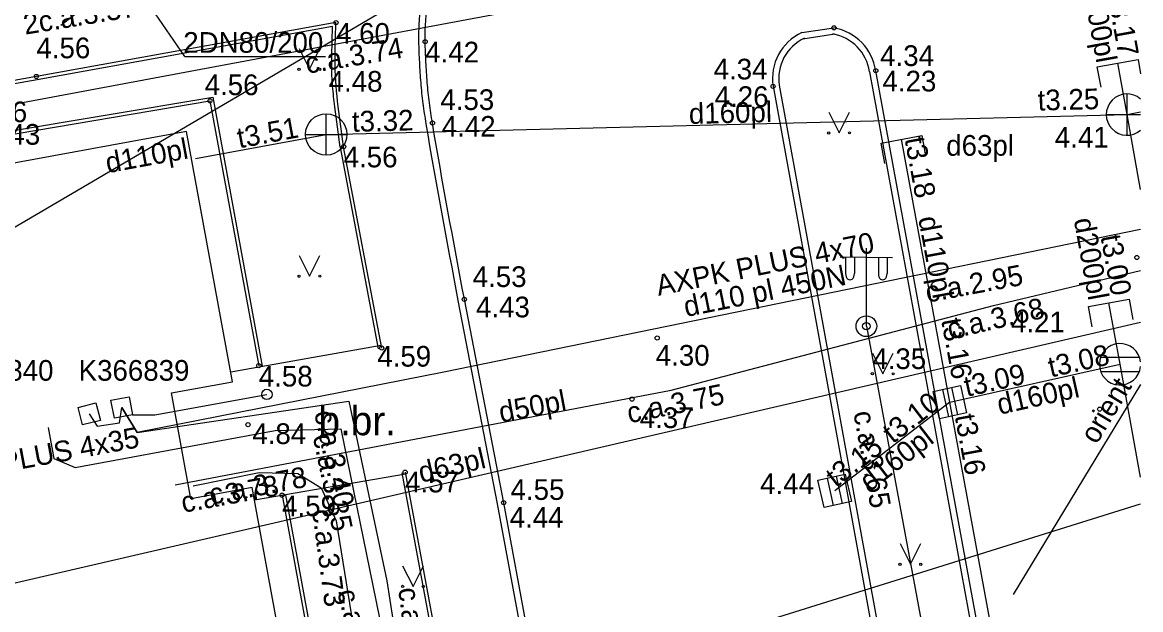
# Model space of a CAD drawing. Extents: x 484635 to 484808, y 278866 to 278977.
# Drawn here: x 484780.57 to 484807.57, y 278884.44 to 278898.63 of the extents above; entities that cross this region are included whole.
import ezdxf

# ---------------------------------------------------------------- set-up
doc = ezdxf.new("R2010")
doc.units = 0
for name, color, linetype in [('APGS_ACRL_####_####_#', 7, 'Continuous'), ('APGS_ELEM_####_####_#', 7, 'Continuous'), ('APGS_ELEM_####_TKST_#', 7, 'Continuous'), ('APGS_VADP_ZSPR_####_I', 7, 'Continuous'), ('BUVE_EKAS_####_####_#', 7, 'Continuous'), ('CELI_CAPM_####_####_#', 7, 'Continuous'), ('CELI_CMAL_####_####_#', 7, 'Continuous'), ('CELI_CSEG_####_TKST_#', 7, 'Continuous'), ('CKOM_ELEM_####_####_#', 7, 'Continuous'), ('CKOM_ZEMJ_####_####_#', 7, 'Continuous'), ('DREN_ELEM_####_####_#', 7, 'Continuous'), ('DREN_VADP_####_####_I', 7, 'Continuous'), ('DREN_VADP_####_TKST_I', 7, 'Continuous'), ('ELEK_ACRL_####_####_#', 7, 'Continuous'), ('ELEK_ACRL_####_TKST_#', 7, 'Continuous'), ('ELEK_ELEM_####_####_#', 7, 'Continuous'), ('ELEK_ELEM_####_TKST_#', 7, 'Continuous'), ('ELEK_VADP_ZSPR_####_I', 7, 'Continuous'), ('ELEK_VADP_ZSPR_TKST_I', 7, 'Continuous'), ('LKAN_ELEM_####_####_#', 7, 'Continuous'), ('LKAN_ELEM_PAST_TKST_#', 7, 'Continuous'), ('LKAN_VADP_PAST_####_#', 7, 'Continuous'), ('LKAN_VADP_PAST_####_I', 7, 'Continuous'), ('LKAN_VADP_PAST_TKST_I', 7, 'Continuous'), ('RELJ_AATZ_####_TKST_#', 7, 'Continuous'), ('RELJ_ELEM_####_####_#', 7, 'Continuous'), ('SAKK_KKAN_####_####_I', 7, 'Continuous'), ('SAKK_KKAN_####_TKST_I', 7, 'Continuous'), ('SAKT_VADP_NEDR_####_#', 7, 'Continuous'), ('SAKT_VADP_NEDR_TKST_#', 7, 'Continuous'), ('SILT_VADP_UDEN_TKST_I', 7, 'Continuous'), ('SKAN_ELEM_####_####_#', 7, 'Continuous'), ('SKAN_ELEM_PAST_TKST_#', 7, 'Continuous'), ('SKAN_VADP_NEDR_####_#', 7, 'Continuous'), ('SKAN_VADP_PAST_####_I', 7, 'Continuous'), ('SKAN_VADP_PAST_TKST_I', 7, 'Continuous'), ('TERT_ELEM_####_####_#', 7, 'Continuous'), ('UDTK_VADP_NEDR_####_#', 7, 'Continuous'), ('UDTK_VADP_UDEN_####_I', 7, 'Continuous'), ('UDTK_VADP_UDEN_TKST_I', 7, 'Continuous')]:
    doc.layers.add(name, color=color, linetype=linetype)

msp = doc.modelspace()

# ---------------------------------------------------------------- linework, layer by layer
at = {"layer": 'APGS_ACRL_####_####_#'}
msp.add_lwpolyline([(484800.949, 278891.291), (484804.267, 278873.397), (484805.658, 278866.043)], dxfattribs=at)
at = {"layer": 'APGS_ELEM_####_####_#'}
for p, q in [((484800.949, 278891.291), (484800.949, 278893.174)), ((484800.949, 278892.958), (484800.314, 278892.953)), ((484800.449, 278892.954), (484800.449, 278892.562)), ((484800.659, 278892.956), (484800.659, 278892.562)), ((484800.949, 278892.958), (484801.584, 278892.953)), ((484801.239, 278892.956), (484801.239, 278892.562)), ((484801.449, 278892.954), (484801.449, 278892.562))]:
    msp.add_line(p, q, dxfattribs=at)
for radius in [0.25, 0.09]:
    msp.add_circle((484800.949, 278891.291), radius, dxfattribs=at)
for centre, major_axis, start_param, end_param in [((484800.554, 278892.562), (0, 0.151), 1.570796, 4.712389), ((484801.344, 278892.562), (0, -0.151), 4.712389, 7.853982)]:
    msp.add_ellipse(centre, major_axis=major_axis, ratio=0.695971, start_param=start_param, end_param=end_param, dxfattribs=at)
at = {"layer": 'APGS_VADP_ZSPR_####_I'}
msp.add_lwpolyline([(484800.949, 278891.291), (484804.267, 278873.397), (484805.658, 278866.043)], dxfattribs=at)
at = {"layer": 'BUVE_EKAS_####_####_#'}
for p, q in [((484784.53, 278895.998), (484773.318, 278893.935)), ((484785.643, 278889.949), (484784.53, 278895.998)), ((484784.168, 278889.678), (484785.643, 278889.949)), ((484784.638, 278887.121), (484784.168, 278889.678)), ((484786.113, 278887.392), (484784.638, 278887.121)), ((484787.226, 278881.344), (484786.113, 278887.392))]:
    msp.add_line(p, q, dxfattribs=at)
at = {"layer": 'CELI_CAPM_####_####_#'}
for p, q in [((484788.14, 278898.629), (484780.905, 278897.327)), ((484788.058, 278898.533), (484780.919, 278897.248)), ((484799.391, 278898.387), (484800.167, 278898.503)), ((484799.413, 278898.238), (484800.19, 278898.355)), ((484780.905, 278897.327), (484773.429, 278895.967)), ((484780.92, 278897.248), (484773.473, 278895.893)), ((484779.629, 278895.897), (484785.162, 278896.83)), ((484785.162, 278896.83), (484786.359, 278890.324)), ((484779.642, 278895.818), (484785.097, 278896.738)), ((484785.097, 278896.738), (484786.275, 278890.335)), ((484789.167, 278890.748), (484788.245, 278895.615)), ((484789.245, 278890.763), (484788.324, 278895.63)), ((484792.044, 278886.996), (484791.093, 278891.913)), ((484792.191, 278887.024), (484791.241, 278891.942)), ((484793.728, 278877.892), (484792.044, 278886.997)), ((484793.875, 278877.919), (484792.191, 278887.024))]:
    msp.add_line(p, q, dxfattribs=at)
for points in [[(484806.787, 278866.043), (484804.221, 278880.039), (484801.029, 278897.438)], [(484806.939, 278866.043), (484804.369, 278880.066), (484801.177, 278897.465)], [(484798.696, 278897.09), (484801.688, 278880.665), (484804.352, 278866.043)], [(484798.844, 278897.117), (484801.835, 278880.691), (484804.505, 278866.043)], [(484789.731, 278887.748), (484790.96, 278881.112), (484791.811, 278876.364)], [(484789.809, 278887.762), (484791.039, 278881.126), (484791.89, 278876.378)], [(484786.839, 278887.208), (484788.016, 278880.789), (484786.643, 278880.516), (484787.532, 278875.724)], [(484786.919, 278887.216), (484788.109, 278880.725), (484786.736, 278880.453), (484787.611, 278875.738)]]:
    msp.add_lwpolyline(points, dxfattribs=at)
for centre, radius, start, end in [((484799.909, 278897.275), 1.227, 115.0118, 188.6452), ((484799.942, 278897.274), 1.249, 8.8004, 79.6267), ((484799.909, 278897.275), 1.077, 115.0118, 188.6452), ((484799.942, 278897.274), 1.099, 8.8004, 79.6267)]:
    msp.add_arc(centre, radius, start, end, dxfattribs=at)
for points in [[(484791.093, 278891.915), (484790.321, 278896.182), (484790.246, 278896.676), (484790.194, 278897.173), (484790.161, 278897.672), (484790.143, 278898.169), (484790.155, 278898.665), (484790.207, 278899.159), (484790.291, 278899.653), (484790.4, 278900.147), (484790.526, 278900.628), (484790.676, 278901.097), (484790.85, 278901.557), (484791.053, 278902.011), (484791.531, 278902.881), (484792.088, 278903.7), (484792.712, 278904.47), (484793.41, 278905.175), (484794.191, 278905.799), (484795.034, 278906.336), (484795.899, 278906.782), (484796.807, 278907.137), (484797.774, 278907.393), (484798.754, 278907.542), (484799.749, 278907.59), (484800.745, 278907.537), (484801.722, 278907.387), (484802.686, 278907.129), (484803.612, 278906.767), (484804.493, 278906.309), (484805.33, 278905.77), (484805.725, 278905.473), (484806.108, 278905.152), (484806.826, 278904.45), (484807.467, 278903.676), (484807.573, 278903.533)], [(484791.241, 278891.942), (484790.47, 278896.202), (484790.395, 278896.69), (484790.344, 278897.182), (484790.312, 278897.674), (484790.294, 278898.166), (484790.306, 278898.654), (484790.357, 278899.141), (484790.44, 278899.626), (484790.546, 278900.112), (484790.671, 278900.586), (484790.818, 278901.047), (484790.99, 278901.5), (484791.19, 278901.947), (484791.66, 278902.803), (484792.209, 278903.61), (484792.823, 278904.369), (484793.511, 278905.062), (484794.279, 278905.676), (484795.109, 278906.205), (484795.961, 278906.645), (484796.854, 278906.993), (484797.805, 278907.246), (484798.769, 278907.392), (484799.749, 278907.439), (484800.729, 278907.387), (484801.691, 278907.239), (484802.639, 278906.986), (484803.55, 278906.629), (484804.418, 278906.178), (484805.242, 278905.648), (484805.631, 278905.355), (484806.008, 278905.039), (484806.715, 278904.347), (484807.346, 278903.586), (484807.573, 278903.274)], [(484788.244, 278895.619), (484788.114, 278896.595), (484788.083, 278896.843), (484788.058, 278897.091), (484788.042, 278897.34), (484788.039, 278897.589), (484788.058, 278898.533)], [(484788.324, 278895.63), (484788.194, 278896.603), (484788.119, 278897.592), (484788.14, 278898.629)]]:
    msp.add_spline(points, degree=3, dxfattribs=at)
at = {"layer": 'CELI_CMAL_####_####_#'}
for points in [[(484785.599, 278890.19), (484789.233, 278890.83)], [(484789.817, 278887.718), (484786.17, 278887.086)]]:
    msp.add_lwpolyline(points, dxfattribs=at)
at = {"layer": 'CKOM_ELEM_####_####_#'}
msp.add_lwpolyline([(484781.496, 278898.57), (484781.852, 278898.842), (484781.421, 278898.963), (484781.777, 278899.235), (484781.346, 278899.356), (484781.702, 278899.628)], dxfattribs=at)
msp.add_circle((484786.472, 278889.643), 0.125, dxfattribs=at)
at = {"layer": 'CKOM_ZEMJ_####_####_#'}
msp.add_lwpolyline([(484783.227, 278889.152), (484783.762, 278889.145), (484786.472, 278889.643)], dxfattribs=at)
at = {"layer": 'DREN_ELEM_####_####_#'}
msp.add_lwpolyline([(484801.398, 278895.226), (484801.307, 278895.718), (484802.291, 278895.899), (484802.381, 278895.407)], dxfattribs=at)
at = {"layer": 'DREN_VADP_####_####_I'}
msp.add_line((484802.968, 278889.456), (484801.799, 278895.808), dxfattribs=at)
msp.add_lwpolyline([(484805.836, 278873.802), (484802.968, 278889.456)], dxfattribs=at)
at = {"layer": 'ELEK_ACRL_####_####_#'}
for points in [[(484807.573, 278893.629), (484790.746, 278890.18), (484783.337, 278888.722), (484782.967, 278889.326)], [(484782.967, 278889.326), (484783.337, 278888.722), (484788.452, 278889.478), (484789.367, 278885.14), (484789.804, 278882.334), (484789.731, 278881.43), (484790.16, 278880.357), (484791.085, 278875.503), (484791.062, 278875.354), (484783.559, 278873.877), (484783.132, 278874.493)], [(484781.185, 278888.845), (484781.329, 278888.091), (484781.841, 278887.878), (484786.673, 278888.772), (484788.257, 278888.812), (484789.576, 278882.339), (484789.452, 278881.33), (484789.936, 278880.279), (484790.808, 278874.869), (484790.648, 278874.587), (484781.611, 278872.941), (484780.931, 278873.356), (484780.833, 278874.148)]]:
    msp.add_lwpolyline(points, dxfattribs=at)
at = {"layer": 'ELEK_ELEM_####_####_#'}
for points in [[(484783.227, 278889.152), (484782.788, 278889.069), (484782.706, 278889.501), (484783.145, 278889.584)], [(484782.453, 278889.015), (484782.021, 278888.904), (484781.911, 278889.33), (484782.343, 278889.441)]]:
    msp.add_lwpolyline(points, close=True, dxfattribs=at)
at = {"layer": 'ELEK_VADP_ZSPR_####_I'}
for points in [[(484807.573, 278893.629), (484790.746, 278890.18), (484783.337, 278888.722), (484782.967, 278889.326)], [(484782.967, 278889.326), (484783.337, 278888.722), (484788.452, 278889.478), (484789.367, 278885.14), (484789.804, 278882.334), (484789.731, 278881.43), (484790.16, 278880.357), (484791.085, 278875.503), (484791.062, 278875.354), (484783.559, 278873.877), (484783.132, 278874.493)], [(484782.182, 278889.172), (484782.371, 278888.872), (484782.912, 278888.959), (484782.967, 278889.326)], [(484781.185, 278888.845), (484781.329, 278888.091), (484781.841, 278887.878), (484786.673, 278888.772), (484788.257, 278888.812), (484789.576, 278882.339), (484789.452, 278881.33), (484789.936, 278880.279), (484790.808, 278874.869), (484790.648, 278874.587), (484781.611, 278872.941), (484780.931, 278873.356), (484780.833, 278874.148)]]:
    msp.add_lwpolyline(points, dxfattribs=at)
at = {"layer": 'LKAN_ELEM_####_####_#'}
for p, q in [((484806.608, 278890.545), (484807.544, 278890.545)), ((484806.608, 278890.195), (484807.544, 278890.195)), ((484802.785, 278889.761), (484802.931, 278889.102)), ((484803.004, 278889.809), (484803.151, 278889.151)), ((484800.001, 278887.618), (484800.148, 278886.959)), ((484800.221, 278887.667), (484800.367, 278887.008))]:
    msp.add_line(p, q, dxfattribs=at)
msp.add_lwpolyline([(484806.403, 278891.273), (484806.314, 278891.765), (484807.297, 278891.944), (484807.387, 278891.453)], dxfattribs=at)
for points in [[(484802.565, 278889.712), (484803.224, 278889.858), (484803.371, 278889.199), (484802.712, 278889.053)], [(484799.781, 278887.569), (484800.44, 278887.716), (484800.587, 278887.057), (484799.928, 278886.911)]]:
    msp.add_lwpolyline(points, close=True, dxfattribs=at)
msp.add_arc((484807.076, 278890.37), 0.5, 6.4718, 353.5282, dxfattribs=at)
at = {"layer": 'LKAN_VADP_PAST_####_#'}
msp.add_line((484807.573, 278887.645), (484807.076, 278890.37), dxfattribs=at)
msp.add_lwpolyline([(484807.076, 278890.37), (484806.806, 278891.855)], dxfattribs=at)
at = {"layer": 'LKAN_VADP_PAST_####_I'}
for q in [(484807.076, 278890.37), (484800.184, 278887.313)]:
    msp.add_line((484802.968, 278889.456), q, dxfattribs=at)
at = {"layer": 'RELJ_ELEM_####_####_#'}
for centre in [(484788.14, 278898.629), (484800.167, 278898.503), (484790.294, 278898.166), (484780.905, 278897.327), (484801.177, 278897.465), (484798.696, 278897.09), (484785.097, 278896.738), (484790.47, 278896.202), (484788.324, 278895.63), (484807.481, 278892.952), (484791.241, 278891.942), (484795.898, 278891.006), (484789.245, 278890.763), (484786.275, 278890.335), (484795.289, 278889.529), (484806.583, 278889.286), (484786.015, 278888.91), (484789.809, 278887.762), (484786.839, 278887.208), (484792.191, 278887.024)]:
    msp.add_circle(centre, 0.05, dxfattribs=at)
at = {"layer": 'SAKK_KKAN_####_####_I'}
for points in [[(484761.895, 278888.193), (484770.872, 278894.886), (484788.535, 278898.187), (484797.166, 278899.809), (484807.573, 278901.643)], [(484784.255, 278887.457), (484796.234, 278889.744), (484804.019, 278891.792), (484807.573, 278892.634)], [(484784.69, 278887.431), (484786.281, 278887.759), (484787.215, 278887.727), (484787.779, 278887.388), (484788.143, 278886.589), (484789.238, 278879.793), (484790.369, 278872.4), (484791.546, 278866.043)]]:
    msp.add_lwpolyline(points, dxfattribs=at)
at = {"layer": 'SAKT_VADP_NEDR_####_#'}
msp.add_lwpolyline([(484807.573, 278889.88), (484804.494, 278884.804)], dxfattribs=at)
at = {"layer": 'SILT_VADP_UDEN_TKST_I'}
msp.add_line((484784.493, 278897.806), (484787.889, 278897.806), dxfattribs=at)
msp.add_lwpolyline([(484784.493, 278897.806), (484783.342, 278899.492)], dxfattribs=at)
at = {"layer": 'SKAN_ELEM_####_####_#'}
for p, q in [((484807.244, 278895.905), (484807.244, 278896.905)), ((484787.904, 278895.425), (484787.904, 278896.425)), ((484806.744, 278896.405), (484807.573, 278896.405)), ((484787.404, 278895.925), (484788.404, 278895.925))]:
    msp.add_line(p, q, dxfattribs=at)
msp.add_lwpolyline([(484806.616, 278897.067), (484806.527, 278897.559), (484807.511, 278897.738), (484807.573, 278897.394)], dxfattribs=at)
msp.add_circle((484787.904, 278895.925), 0.5, dxfattribs=at)
msp.add_arc((484807.244, 278896.405), 0.5, 48.8851, 311.1149, dxfattribs=at)
at = {"layer": 'SKAN_VADP_NEDR_####_#'}
msp.add_lwpolyline([(484756.132, 278870.921), (484807.573, 278886.997)], dxfattribs=at)
at = {"layer": 'SKAN_VADP_PAST_####_I'}
for p, q in [((484807.573, 278894.592), (484807.244, 278896.405)), ((484784.75, 278895.344), (484787.904, 278895.925))]:
    msp.add_line(p, q, dxfattribs=at)
for points in [[(484807.244, 278896.405), (484807.019, 278897.648)], [(484787.904, 278895.925), (484807.244, 278896.405)], [(484807.244, 278896.405), (484807.573, 278896.473)]]:
    msp.add_lwpolyline(points, dxfattribs=at)
at = {"layer": 'TERT_ELEM_####_####_#'}
for p, q in [((484787.25, 278898), (484787.5, 278897.5)), ((484787.5, 278897.5), (484787.75, 278898)), ((484800.042, 278896.464), (484800.292, 278895.964)), ((484800.292, 278895.964), (484800.542, 278896.464)), ((484787.25, 278893), (484787.5, 278892.5)), ((484787.5, 278892.5), (484787.75, 278893)), ((484801.097, 278890.641), (484801.347, 278890.141)), ((484801.347, 278890.141), (484801.597, 278890.641)), ((484801.763, 278886.036), (484802.013, 278885.536)), ((484802.013, 278885.536), (484802.263, 278886.036)), ((484789.75, 278885.5), (484790, 278885)), ((484790, 278885), (484790.25, 278885.5))]:
    msp.add_line(p, q, dxfattribs=at)
for centre, radius in [((484787.25, 278897.5), 0.028), ((484787.75, 278897.5), 0.0263), ((484800.042, 278895.963), 0.028), ((484800.542, 278895.963), 0.0263), ((484787.25, 278892.5), 0.028), ((484787.75, 278892.5), 0.0263), ((484801.097, 278890.141), 0.028), ((484801.597, 278890.141), 0.0263), ((484801.763, 278885.535), 0.028), ((484802.263, 278885.535), 0.0263), ((484789.75, 278885), 0.028), ((484790.25, 278885), 0.0263)]:
    msp.add_circle(centre, radius, dxfattribs=at)
at = {"layer": 'UDTK_VADP_NEDR_####_#'}
msp.add_lwpolyline([(484753.238, 278876.403), (484757.275, 278880.118), (484799.521, 278904.942)], dxfattribs=at)
at = {"layer": 'UDTK_VADP_UDEN_####_I'}
msp.add_lwpolyline([(484807.573, 278891.378), (484776.243, 278884.118)], dxfattribs=at)

# ---------------------------------------------------------------- texts
at = {"layer": 'APGS_ELEM_####_TKST_#'}
msp.add_text('c.a.3.65', height=0.5, rotation=280.23, dxfattribs=at).set_placement((484800.634, 278889.203))
at = {"layer": 'CELI_CSEG_####_TKST_#'}
msp.add_text('b.br.', height=0.7, dxfattribs=at).set_placement((484787.717, 278888.656))
at = {"layer": 'DREN_VADP_####_TKST_I'}
for s, rotation, p in [('t3.18', 280.4235, (484801.871, 278895.819)), ('d110pl', 280.4235, (484802.2, 278893.905)), ('t3.16', 280.4235, (484802.755, 278891.44)), ('t3.16', 280.3837, (484803.082, 278889.123))]:
    msp.add_text(s, height=0.5, rotation=rotation, dxfattribs=at).set_placement(p)
at = {"layer": 'ELEK_ACRL_####_TKST_#'}
for s, rotation, p in [('d110 pl 450N', 11.3998, (484796.594, 278891.512)), ('c.a.2.95', 10.5208, (484802.426, 278891.86)), ('c.a.3.40', 282.0022, (484787.61, 278889.204)), ('c.a.3.35', 281.8159, (484787.577, 278888.63)), ('c.a.3.30', 284.2745, (484788.165, 278884.87)), ('c.a.3.33', 277.4256, (484789.641, 278884.947))]:
    msp.add_text(s, height=0.5, rotation=rotation, dxfattribs=at).set_placement(p)
at = {"layer": 'ELEK_ELEM_####_TKST_#'}
for s, p in [('K366840', (484778.64, 278889.973)), ('K366839', (484781.924, 278889.973))]:
    msp.add_text(s, height=0.5, dxfattribs=at).set_placement(p)
at = {"layer": 'ELEK_VADP_ZSPR_TKST_I'}
for s, rotation, p in [('AXPK PLUS 4x70', 11.3998, (484795.926, 278892.024)), ('AXPK PLUS 4x35', 10.529, (484778.157, 278887.392))]:
    msp.add_text(s, height=0.5, rotation=rotation, dxfattribs=at).set_placement(p)
at = {"layer": 'LKAN_ELEM_PAST_TKST_#'}
for s, p in [('4.21', (484804.441, 278891.142)), ('4.35', (484801.092, 278890.255)), ('4.44', (484798.383, 278887.233))]:
    msp.add_text(s, height=0.5, dxfattribs=at).set_placement(p)
at = {"layer": 'LKAN_VADP_PAST_TKST_I'}
for s, rotation, p in [('d200pl', 280.3324, (484805.956, 278893.866)), ('t3.00', 280.3324, (484806.603, 278893.462)), ('t3.08', 12.5473, (484805.403, 278890.05)), ('t3.09', 12.5473, (484803.373, 278889.583)), ('d160pl', 12.5473, (484804.167, 278889.149)), ('t3.10', 37.5807, (484801.587, 278888.436)), ('d160pl', 37.5807, (484801.028, 278887.275)), ('t3.15', 37.5807, (484800.215, 278887.372))]:
    msp.add_text(s, height=0.5, rotation=rotation, dxfattribs=at).set_placement(p)
at = {"layer": 'RELJ_AATZ_####_TKST_#'}
for s, p in [('4.60', (484788.14, 278898.118)), ('4.56', (484780.905, 278897.767)), ('4.42', (484790.294, 278897.666)), ('4.34', (484801.282, 278897.58)), ('4.34', (484797.26, 278897.255)), ('4.56', (484784.967, 278896.876)), ('4.23', (484801.338, 278896.965)), ('4.26', (484797.285, 278896.59)), ('4.53', (484790.66, 278896.516)), ('4.56', (484779.382, 278896.221)), ('4.42', (484790.693, 278895.871)), (' 4.43', (484779.511, 278895.677)), ('4.56', (484788.324, 278895.13)), ('4.53', (484791.441, 278892.238)), ('4.43', (484791.521, 278891.505)), ('4.59', (484789.137, 278890.314)), ('4.30', (484795.863, 278890.337)), ('4.58', (484786.275, 278889.833)), (' 4.37', (484795.289, 278888.829)), ('4.84', (484786.12, 278888.443)), ('4.57', (484789.809, 278887.274)), ('4.55', (484792.356, 278887.093)), ('4.59', (484786.839, 278886.698)), ('4.44', (484792.335, 278886.424))]:
    msp.add_text(s, height=0.5, dxfattribs=at).set_placement(p)
at = {"layer": 'SAKK_KKAN_####_TKST_I'}
for s, rotation, p in [('c.a.3.74', 9.5341, (484787.443, 278897.391)), ('c.a.3.68', 12.9047, (484802.966, 278890.97)), ('d50pl', 10.808, (484792.125, 278888.96)), ('c.a.3.75', 11.4269, (484795.222, 278888.943)), ('c.a.3.78', 10.611, (484785.13, 278886.976)), ('c.a.3.78', 10.4542, (484784.45, 278886.779)), ('c.a.3.73', 277.5882, (484787.56, 278886.842))]:
    msp.add_text(s, height=0.5, rotation=rotation, dxfattribs=at).set_placement(p)
at = {"layer": 'SAKT_VADP_NEDR_TKST_#'}
msp.add_text('orient', height=0.5, rotation=58.7591, dxfattribs=at).set_placement((484806.509, 278888.415))
at = {"layer": 'SILT_VADP_UDEN_TKST_I'}
msp.add_text('2c.a.3.37', height=0.5, rotation=9.3439, dxfattribs=at).set_placement((484780.632, 278898.336))
msp.add_text('2DN80/200', height=0.5, dxfattribs=at).set_placement((484784.451, 278897.899))
at = {"layer": 'SKAN_ELEM_PAST_TKST_#'}
for s, p in [('4.48', (484787.961, 278896.959)), ('4.41', (484805.501, 278895.609))]:
    msp.add_text(s, height=0.5, dxfattribs=at).set_placement(p)
at = {"layer": 'SKAN_VADP_PAST_TKST_I'}
for s, rotation, p in [('d200pl', 280.2797, (484806.151, 278899.605)), ('t3.17', 280.2797, (484806.779, 278899.243)), ('t3.25', 1.4225, (484805.092, 278896.502)), ('t3.32', 1.4225, (484788.53, 278895.988)), ('d160pl', 1.4225, (484796.668, 278896.177)), ('t3.51', 10.4375, (484785.802, 278895.589)), ('d110pl', 10.4375, (484782.625, 278894.988))]:
    msp.add_text(s, height=0.5, rotation=rotation, dxfattribs=at).set_placement(p)
at = {"layer": 'UDTK_VADP_UDEN_TKST_I'}
msp.add_text('d63pl', height=0.5, dxfattribs=at).set_placement((484802.878, 278895.411))
msp.add_text('d63pl', height=0.5, rotation=13.0463, dxfattribs=at).set_placement((484790.196, 278887.505))

doc.saveas('drawing.dxf')
